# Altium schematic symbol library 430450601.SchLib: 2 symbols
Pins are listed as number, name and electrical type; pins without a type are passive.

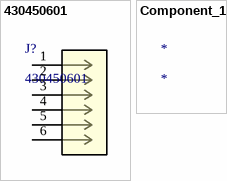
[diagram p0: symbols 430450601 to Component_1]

## 430450601
designator J?
No Description Available; Mfr_Name: Molex Connector Corporation
footprint CON_430450601_MOL
pins: 1, 2, 3, 4, 5, 6

## Component_1
designator *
